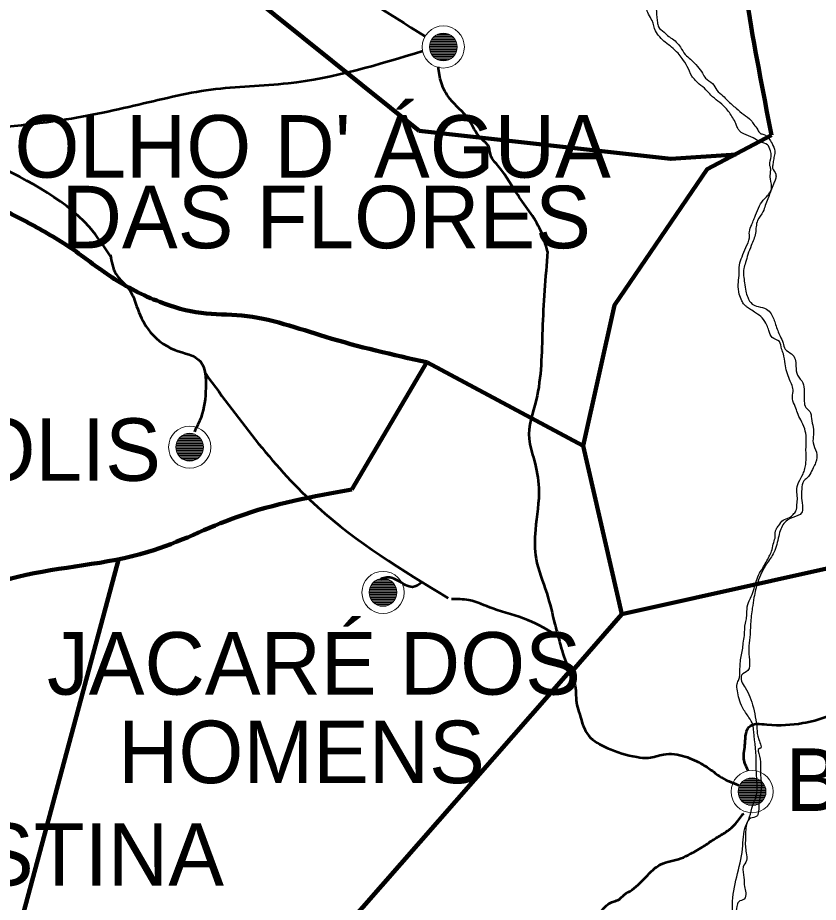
# Model space of a CAD drawing. Extents: x 512883 to 1063249, y 8784064 to 9081064.
# Drawn here: x 688095 to 707317, y 8927073 to 8948300 of the extents above; entities that cross this region are included whole.
import ezdxf

# ---------------------------------------------------------------- set-up
doc = ezdxf.new("R2010")
doc.units = 0
doc.header["$LTSCALE"] = 600
for name, color, linetype, lineweight in [('10', 7, 'Continuous', 53), ('13', 7, 'Continuous', 90), ('4', 7, 'Continuous', 13), ('5', 7, 'Continuous', 13)]:
    doc.layers.add(name, color=color, linetype=linetype, lineweight=lineweight)

msp = doc.modelspace()

# ---------------------------------------------------------------- linework, layer by layer
at = {"layer": '10'}
for points in [[(689387.2, 8953163.3), (691341.7, 8951522.8), (693270.8, 8950625.6), (695174.5, 8949549.1), (697867.2, 8947854.1)], [(687492.6, 8945658.8), (688879.6, 8945806.7), (690884.8, 8946191.2), (692737.8, 8946575.7), (694590.7, 8946729.4), (697823.6, 8947505.2)], [(700816.6, 8942693.1), (700652.2, 8943185.8), (700061.2, 8944106.2), (699587.3, 8944793.9), (699459.9, 8944964.6), (699403.8, 8945202.5), (699220.4, 8945399), (698914.7, 8945869.5), (698471.3, 8946355.6), (698267.5, 8946738.3), (698194, 8947123.6)], [(690354.9, 8942526.3), (689817.4, 8943269.9), (687295.1, 8944922.2), (686757.6, 8945211.3), (686340.8, 8945414.9), (685973.5, 8945577)], [(700816.6, 8942693.1), (700693, 8940812.2), (700540.1, 8939121.3), (700372, 8938190.5), (700494.3, 8937678.6), (700606.4, 8937016.7), (700524.8, 8936008.3), (700540.1, 8935315.4), (700794.9, 8934493.2), (700993.6, 8933743.4), (701036.1, 8933582.5)], [(690322.3, 8942610.4), (690456.1, 8942146.4), (690787.3, 8941758.6), (690950.3, 8941375.9), (691225.5, 8940827.8), (691862.4, 8940331.3), (692484.1, 8940046.9), (692611.5, 8939416.1), (692499.4, 8938718), (692336.3, 8938366.3)], [(692609, 8939750.7), (695293, 8936561.1), (698430.6, 8934369.6)], [(697805.9, 8934752.1), (697574.5, 8934638), (697233.1, 8934788), (696958, 8934865.6), (696810.2, 8934829.4)], [(701069.7, 8933455.2), (700341.4, 8933846.9), (699500.6, 8934120.9), (698929.9, 8934322.6), (698507.1, 8934350)], [(705631.1, 8930230.6), (705530.4, 8930515.7), (705560.6, 8930887.2), (705580.7, 8931126.5), (705651.2, 8931279.2), (706079.1, 8931340.2), (706945, 8931375.9), (707518.9, 8931533.7), (708027.3, 8931813.6), (708611.3, 8932246.3), (709220.4, 8932622.9), (710076.2, 8933014.9), (710730.7, 8933233.8), (711173.7, 8933376.3), (711531.1, 8933529), (711651.9, 8933641), (711767.7, 8933839.5)], [(701072.5, 8933444.7), (701126.1, 8933241.8), (701304.5, 8932709.2), (701477.7, 8932264.5), (701518.5, 8931814.6), (701589.8, 8931581.9)], [(701589.8, 8931581.9), (701805.1, 8931070.5), (702253.2, 8930775.2), (702957.9, 8930561.5), (703239.8, 8930541.1), (703602.3, 8930622.6), (704115.8, 8930571.7), (704543.7, 8930378.2), (704805.5, 8930200.1), (704941.4, 8930098.3), (705407, 8929884.1)], [(702542.1, 8927145.8), (702650.8, 8927247.8), (702847.2, 8927375.1), (703033.4, 8927532.9), (703285.2, 8927792.5), (703526.8, 8927980.8), (704020.1, 8928128.4), (704251.7, 8928235.3), (704563.8, 8928418.6), (704805.5, 8928581.4), (705042.1, 8928724), (705248.5, 8928876.7), (705394.5, 8929039.6), (705485.1, 8929161.7), (705525.3, 8929207.5)], [(699180.2, 8922335.2), (699279.3, 8922437.7), (700515.1, 8923808), (701074.5, 8924523), (701338.9, 8925044.3), (701496.6, 8925640.1), (701700, 8926116.7), (701878, 8926494), (702091.5, 8926841.5), (702406.8, 8927094.8), (702534, 8927139.4), (702559.4, 8927159.3)]]:
    msp.add_spline(points, degree=3, dxfattribs=at)
at = {"layer": '13'}
for p, q in [((687755.8, 8953591.1), (697735.1, 8945585.3)), ((696113.8, 8936977.5), (697917.7, 8940030.2)), ((702603.1, 8933984.9), (712216.4, 8936132.7)), ((690521.2, 8935319.2), (687473.3, 8923993.3)), ((693793.1, 8924010.3), (701341.8, 8932609.5))]:
    msp.add_line(p, q, dxfattribs=at)
for points in [[(705341.3, 8945013.4), (703779.5, 8944911.3), (697735.1, 8945585.3)], [(701670.1, 8938028.7), (702420.6, 8941398.5), (704651.7, 8944666.2), (706193.2, 8945483.1)], [(701360.5, 8932563.1), (702603.1, 8933984.9), (701670.1, 8938028.7), (697917.7, 8940030.2)]]:
    msp.add_lwpolyline(points, dxfattribs=at)
for points in [[(706193.2, 8945483.1), (705605, 8948689.6), (704935.7, 8952345.3), (703718.7, 8955735.6), (702857.6, 8958494.4)], [(697917.7, 8940030.2), (695483.7, 8940642.8), (693475.6, 8941153.4), (692502.1, 8941214.7), (691508.2, 8941480.2), (690352, 8942072.5), (689439.3, 8942726), (688425.1, 8943338.7), (687411, 8943890.1), (686640.2, 8944421.1), (686133.1, 8944850), (685950.6, 8945197.2), (685281.2, 8945626.1), (684530.7, 8946136.7), (683760, 8946504.3), (683151.5, 8946892.3), (682482.1, 8947362.1), (681691.1, 8947913.5), (680940.6, 8948117.7), (679804.7, 8948342.4), (678932.6, 8948669.2), (678381, 8948825.9)], [(680828.7, 8933919), (683954.5, 8933899.9), (685486.5, 8934104.2), (688100.7, 8934885), (691225.8, 8935479.3), (693370.2, 8936322.6), (696113.8, 8936977.5)]]:
    msp.add_spline(points, degree=3, dxfattribs=at)
at = {"layer": '4', "lineweight": 25}
for points in [[(706280.5, 8935814.4), (706310.7, 8936038.4), (706366.1, 8936114.7), (706471.8, 8936242), (706622.8, 8936303.1), (706713.4, 8936379.4), (706778.9, 8936465.9), (706804, 8936618.6), (706814.1, 8936781.5), (706799, 8936944.4), (706844.3, 8937148), (706950, 8937351.6), (706995.3, 8937478.9), (707020.5, 8937616.3), (707020.5, 8937931.9), (707025.5, 8938216.9), (706990.3, 8938435.8), (706894.6, 8938649.6), (706814.1, 8938817.5), (706763.8, 8938970.2), (706693.3, 8939153.5), (706713.4, 8939331.6), (706627.8, 8939616.7), (706517.1, 8939993.3), (706476.8, 8940232.6), (706436.5, 8940354.7), (706381.2, 8940527.8), (706210, 8940624.5), (706129.5, 8940792.5), (706079.1, 8940919.7), (705968.4, 8941097.9), (705812.3, 8941215), (705686.4, 8941301.5), (705595.8, 8941362.6), (705540.5, 8941413.5), (705480, 8941505.1), (705419.6, 8941668), (705394.5, 8941897), (705414.6, 8942110.8), (705424.7, 8942365.3), (705485.1, 8942558.7), (705575.7, 8942787.8), (705661.3, 8943016.8), (705661.3, 8943164.4), (705716.7, 8943327.3), (705767, 8943459.7), (705812.3, 8943561.5), (705902.9, 8943785.4), (706028.8, 8943958.5), (706109.3, 8944045), (706159.7, 8944121.4), (706189.9, 8944187.6), (706164.7, 8944431.9), (706169.7, 8944589.7), (706169.7, 8944691.5), (706149.6, 8944767.8), (706184.8, 8944971.4), (706164.7, 8945108.8), (706094.2, 8945251.4), (705923.1, 8945317.5), (705751.9, 8945419.3), (705525.3, 8945511), (705419.6, 8945592.4), (705374.3, 8945663.7), (705334.1, 8945760.4), (705263.6, 8945897.8), (705087.4, 8946137), (704906.2, 8946299.9), (704740, 8946437.3), (704619.2, 8946569.7), (704458.1, 8946707.1), (704281.9, 8946900.6), (704171.2, 8947129.6), (704050.3, 8947323), (703949.7, 8947445.2), (703793.6, 8947592.8), (703642.6, 8947709.9), (703511.7, 8947837.1), (703411, 8947984.7), (703325.4, 8948229.1), (703189.5, 8948539.6), (703194.5, 8948651.5), (703184.5, 8948855.1), (703154.3, 8948977.3), (703070.3, 8949270.7)], [(703346.2, 8949332.2), (703306.6, 8949057.1), (703254.9, 8948814.4), (703275.1, 8948748.2), (703283.7, 8948698.3), (703421.1, 8948498.8), (703436.2, 8948320.7), (703456.3, 8948193.4), (703476.5, 8948081.4), (703612.4, 8947954.2), (703728.2, 8947847.3), (703783.5, 8947811.7), (703904.3, 8947715), (704005, 8947592.8), (704120.8, 8947419.7), (704246.7, 8947302.7), (704412.8, 8947129.6), (704538.7, 8946966.7), (704609.1, 8946849.7), (704775.3, 8946717.3), (704881, 8946559.5), (705027, 8946427.2), (705137.7, 8946310.1), (705344.1, 8946126.9), (705525.3, 8945974.2), (705701.6, 8945836.7), (705767, 8945740), (705862.6, 8945612.8), (705918, 8945526.2), (706008.6, 8945500.8), (706129.5, 8945399), (706205, 8945281.9), (706270.4, 8945093.6), (706270.4, 8945042.7), (706245.2, 8944910.3), (706225.1, 8944788.2), (706220.1, 8944691.5), (706295.6, 8944543.8), (706295.6, 8944452.2), (706260.3, 8944350.4), (706189.9, 8944182.5), (706104.3, 8943953.4), (706043.9, 8943795.6), (705988.5, 8943642.9), (705857.6, 8943434.2), (705807.3, 8943128.8), (705706.6, 8942833.6), (705626, 8942614.7), (705570.7, 8942426.4), (705525.3, 8942278.8), (705545.5, 8941937.7), (705575.7, 8941734.1), (705621, 8941591.6), (705726.7, 8941428.7), (705872.7, 8941367.7), (706074.1, 8941306.6), (706184.8, 8941194.6), (706290.5, 8940935), (706401.3, 8940655.1), (706471.8, 8940492.2), (706522.1, 8940349.7), (706673.1, 8940232.6), (706758.7, 8940105.3), (706778.9, 8939937.3), (706819.1, 8939718.5), (706945, 8939540.3), (706975.2, 8939336.7), (706980.2, 8939092.4), (707015.5, 8938949.9), (707111.1, 8938853.2), (707151.4, 8938680.1), (707191.7, 8938466.3), (707201.7, 8938288.2), (707191.7, 8938099.8), (707272.2, 8937875.9), (707252.1, 8937621.4), (707196.7, 8937499.2), (707111.1, 8937336.3), (707040.6, 8937249.8), (706970.2, 8937183.6), (706919.8, 8936985.1), (706914.8, 8936771.3), (706940, 8936537.2), (706914.8, 8936420.1), (706703.3, 8936308.1), (706491.9, 8936165.6), (706366.1, 8935860.2), (706250.3, 8935468.3), (706074.1, 8935193.4), (705862.6, 8934755.7), (705772, 8934389.2)], [(703249.9, 8922005.1), (703315.3, 8922091.6), (703365.7, 8922234.1), (703406, 8922351.2), (703446.2, 8922493.7), (703491.6, 8922631.2), (703541.9, 8922763.5), (703602.3, 8922839.9), (703657.7, 8922946.8), (703708, 8923007.8), (703843.9, 8923079.1), (703964.8, 8923140.2), (704025.2, 8923206.3), (704060.4, 8923247.1), (704176.2, 8923328.5), (704231.6, 8923399.8), (704332.2, 8923486.3), (704473.2, 8923588.1), (704659.5, 8923761.2), (704795.4, 8923908.8), (704931.3, 8924071.7), (705027, 8924239.6), (705087.4, 8924422.9), (705137.7, 8924677.4), (705157.9, 8924886.1), (705137.7, 8924998), (705087.4, 8925150.7), (705082.3, 8925272.9), (705072.3, 8925481.6), (705147.8, 8925756.5), (705213.2, 8925990.6), (705213.2, 8926250.2), (705218.3, 8926458.9), (705253.5, 8926759.2), (705253.5, 8927013.7), (705495.2, 8928357.5), (705575.7, 8928912.3), (705666.3, 8929121), (705741.8, 8929400.9), (705827.4, 8929619.8), (705847.5, 8929899.8), (705837.5, 8930062.7), (705827.4, 8930251), (705827.4, 8930383.3), (705767, 8931167.2), (705741.8, 8931330.1), (705651.2, 8931508.2), (705495.2, 8931747.4), (705414.6, 8931956.2), (705374.3, 8932144.5), (705369.3, 8932317.5), (705409.6, 8932419.3), (705434.7, 8932633.1), (705464.9, 8932974.2), (705495.2, 8933131.9), (705515.3, 8933294.8), (705540.5, 8933473), (705565.6, 8933773.3), (705595.8, 8933910.7), (705600.9, 8934053.2), (705641.1, 8934267), (705706.6, 8934409.6), (705777.1, 8934603), (705817.3, 8934750.6), (705882.8, 8934923.7), (705983.5, 8935096.7), (706064, 8935234.1), (706139.5, 8935376.7), (706194.9, 8935498.8), (706235.2, 8935666.8), (706280.5, 8935814.4)], [(705772, 8934389.2), (705731.8, 8934134.7), (705691.5, 8933752.9), (705671.3, 8933427.2), (705646.2, 8933157.4), (705661.3, 8932892.7), (705621, 8932633.1), (705475, 8932521.1), (705475, 8932378.6), (705560.6, 8932225.9), (705676.4, 8932002), (705756.9, 8931742.4), (705817.3, 8931452.2), (705842.5, 8931243.5), (705887.8, 8930978.9), (705908, 8930760), (705902.9, 8930760), (705902.9, 8930581.8), (705928.1, 8930327.3), (705928.1, 8930113.6), (705948.2, 8929930.3), (705913, 8929584.2), (705887.8, 8929406), (705872.7, 8929202.4), (705842.5, 8929141.3), (705686.4, 8929090.4), (705595.8, 8928942.8), (705565.6, 8928591.6), (705565.6, 8928418.6), (705585.8, 8928260.8), (705590.8, 8928072.4), (705515.3, 8927924.8), (705530.4, 8927665.2), (705540.5, 8927451.4), (705575.7, 8927303.8), (705535.4, 8927151.1), (705404.5, 8927085), (705359.2, 8926973), (705329, 8926774.5), (705329, 8926479.2), (705354.2, 8926280.7), (705329, 8926072), (705298.8, 8925904.1), (705313.9, 8925736.1), (705313.9, 8925466.3), (705303.8, 8925267.8), (705268.6, 8925099.8), (705213.2, 8924926.8), (705203.2, 8924718.1), (705198.1, 8924422.9), (705188.1, 8924260), (705072.3, 8924030.9), (704966.6, 8923817.2), (704790.4, 8923664.4), (704493.3, 8923389.6), (704333.1, 8923283.1)]]:
    msp.add_spline(points, degree=3, dxfattribs=at)
at = {"layer": '5'}
for p, q in [((698021.2, 8947757), (698605.9, 8947757)), ((698039.5, 8947787), (698587.6, 8947787)), ((698063.5, 8947817), (698563.9, 8947817)), ((698092.6, 8947847), (698534.2, 8947847)), ((698132.2, 8947877), (698494.6, 8947877)), ((698189.5, 8947907), (698437.3, 8947907)), ((697981, 8947607), (698645.8, 8947607)), ((697981.6, 8947577), (698645.5, 8947577)), ((697983.1, 8947637), (698643.7, 8947637)), ((697984.6, 8947547), (698642.2, 8947547)), ((697987.9, 8947667), (698638.9, 8947667)), ((697996, 8947697), (698630.8, 8947697)), ((698006.8, 8947727), (698620, 8947727.3)), ((697990.6, 8947517), (698636.2, 8947517)), ((697999.6, 8947487), (698627.2, 8947487)), ((698012.2, 8947457), (698614.9, 8947457.3)), ((698028.1, 8947427), (698598.7, 8947427)), ((698048.8, 8947397), (698578.3, 8947397.3)), ((698074, 8947366.7), (698553.1, 8947367)), ((698107.3, 8947337), (698519.5, 8947337)), ((698152.3, 8947307), (698474.5, 8947307)), ((698226.1, 8947277), (698400.4, 8947277)), ((691950.3, 8938183), (692498.4, 8938183)), ((691974.3, 8938213), (692474.7, 8938213)), ((692003.4, 8938243), (692445, 8938243)), ((692043, 8938273), (692405.4, 8938273)), ((692100.3, 8938303), (692348.1, 8938303)), ((691891.8, 8938003), (692556.6, 8938003)), ((691892.4, 8937973), (692556.3, 8937973)), ((691893.9, 8938033), (692554.5, 8938033)), ((691898.7, 8938063), (692549.7, 8938063)), ((691906.8, 8938093), (692541.6, 8938093)), ((691917.6, 8938123), (692530.8, 8938123.3)), ((691932, 8938153), (692516.7, 8938153)), ((691895.4, 8937943), (692553, 8937943)), ((691901.4, 8937913), (692547, 8937913)), ((691910.4, 8937883), (692538, 8937883)), ((691923, 8937853), (692525.7, 8937853.3)), ((691938.9, 8937823), (692509.5, 8937823)), ((691959.6, 8937793), (692489.1, 8937793.3)), ((691984.8, 8937762.7), (692463.9, 8937763)), ((692018.1, 8937733), (692430.3, 8937733)), ((692063.1, 8937703), (692385.3, 8937703)), ((692136.9, 8937673), (692311.2, 8937673)), ((696685, 8934787.8), (697047.4, 8934787.8)), ((696742.3, 8934817.8), (696990.1, 8934817.8)), ((696540.7, 8934577.8), (697191.7, 8934577.8)), ((696548.8, 8934607.8), (697183.6, 8934607.8)), ((696559.6, 8934637.8), (697172.8, 8934638.1)), ((696574, 8934667.8), (697158.7, 8934667.8)), ((696592.3, 8934697.8), (697140.4, 8934697.8)), ((696616.3, 8934727.8), (697116.7, 8934727.8)), ((696645.4, 8934757.8), (697087, 8934757.8)), ((696533.8, 8934517.8), (697198.6, 8934517.8)), ((696534.4, 8934487.8), (697198.3, 8934487.8)), ((696535.9, 8934547.8), (697196.5, 8934547.8)), ((696537.4, 8934457.8), (697195, 8934457.8)), ((696543.4, 8934427.8), (697189, 8934427.8)), ((696552.4, 8934397.8), (697180, 8934397.8)), ((696565, 8934367.8), (697167.7, 8934368.1)), ((696580.9, 8934337.8), (697151.5, 8934337.8)), ((696601.6, 8934307.8), (697131.1, 8934308.1)), ((696626.8, 8934277.4), (697105.9, 8934277.8)), ((696660.1, 8934247.8), (697072.3, 8934247.8)), ((696705.1, 8934217.8), (697027.3, 8934217.8)), ((696778.9, 8934187.8), (696953.2, 8934187.8)), ((705452.8, 8929916.9), (706000.9, 8929916.9)), ((705476.8, 8929946.9), (705977.2, 8929946.9)), ((705505.9, 8929976.9), (705947.5, 8929976.9)), ((705545.5, 8930006.9), (705907.9, 8930006.9)), ((705602.8, 8930036.9), (705850.6, 8930036.9)), ((705394.3, 8929736.9), (706059.1, 8929736.9)), ((705394.9, 8929706.9), (706058.8, 8929706.9)), ((705396.4, 8929766.9), (706057, 8929766.9)), ((705401.2, 8929796.9), (706052.2, 8929796.9)), ((705409.3, 8929826.9), (706044.1, 8929826.9)), ((705420.1, 8929856.9), (706033.3, 8929857.2)), ((705434.5, 8929886.9), (706019.2, 8929886.9)), ((705397.9, 8929676.9), (706055.5, 8929676.9)), ((705403.9, 8929646.9), (706049.5, 8929646.9)), ((705412.9, 8929616.9), (706040.5, 8929616.9)), ((705425.5, 8929586.9), (706028.2, 8929587.2)), ((705441.4, 8929556.9), (706012, 8929556.9)), ((705462.1, 8929526.9), (705991.6, 8929527.2)), ((705487.3, 8929496.6), (705966.4, 8929496.9)), ((705520.6, 8929466.9), (705932.8, 8929466.9)), ((705565.6, 8929436.9), (705887.8, 8929436.9)), ((705639.4, 8929406.9), (705813.7, 8929406.9))]:
    msp.add_line(p, q, dxfattribs=at)
for centre, radius in [((698313.5, 8947598), 506.1), ((698313.5, 8947598), 332.9), ((692224.3, 8937994), 506.1), ((692224.3, 8937994), 332.9), ((696866.3, 8934508.7), 506.1), ((696866.3, 8934508.7), 332.9), ((705726.8, 8929727.9), 506.1), ((705726.8, 8929727.9), 332.9)]:
    msp.add_circle(centre, radius, dxfattribs=at)

# ---------------------------------------------------------------- texts
for s, p in [("OLHO D' ÁGUA", (688018.3, 8944462.4)), ('DAS FLORES', (689149.5, 8942766.6)), ('MONTEIRÓPOLIS', (674815.8, 8937186.6)), ('JACARÉ DOS ', (688798.7, 8932056.1)), ('HOMENS', (690506.1, 8929931.8)), ('BATALHA', (706526.6, 8929265.9)), ('PALESTINA', (682012.2, 8927470.7))]:
    msp.add_text(s, height=1500, dxfattribs=at).set_placement(p)

doc.saveas('drawing.dxf')
